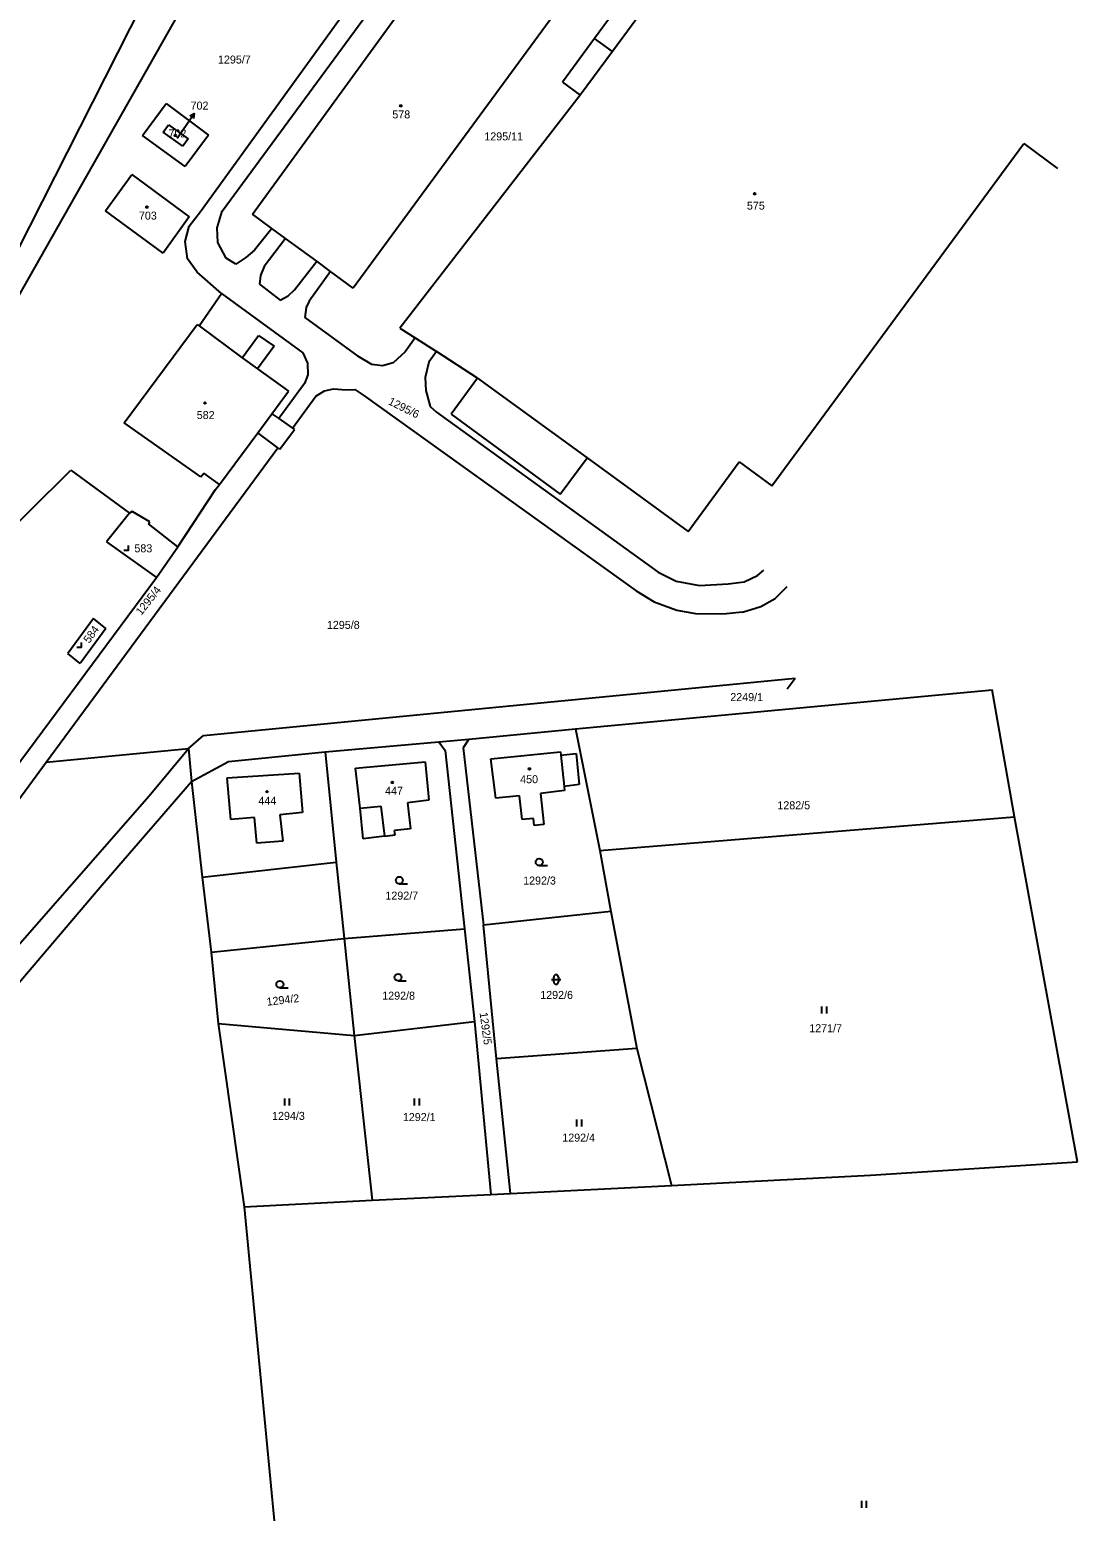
# Model space of a CAD drawing. Extents: x -717507 to -715515, y -957700 to -954941.
# Drawn here: x -716724.1 to -716501.6, y -957047 to -956732.3 of the extents above; entities that cross this region are included whole.
import ezdxf

# ---------------------------------------------------------------- set-up
doc = ezdxf.new("R2010")
doc.units = 0
for name, color, linetype in [('Hranice parcel', 7, 'Continuous'), ('Parcelní čísla', 7, 'Continuous'), ('Pop  PČ popisy', 7, 'Continuous'), ('Vnitřní kresba', 7, 'Continuous'), ('Značky budov', 7, 'Continuous'), ('Značky kultur', 7, 'Continuous')]:
    doc.layers.add(name, color=color, linetype=linetype)

msp = doc.modelspace()

# ---------------------------------------------------------------- linework, layer by layer
at = {"layer": 'Hranice parcel'}
for points in [[(-716687.81, -956770.92), (-716623.91, -956682.42)], [(-716676.78, -956771.51), (-716629.89, -956706.87)], [(-716774.89, -956874.26), (-716692.04, -956710.7)], [(-716774.89, -956874.26), (-716682.29, -956710.93)], [(-716597.24, -956724.68), (-716604.17, -956734.14)], [(-716612.06, -956728.11), (-716655.41, -956787.18)], [(-716604.17, -956734.14), (-716611, -956743.46)], [(-716611, -956743.46), (-716607.19, -956746.24)], [(-716607.19, -956746.24), (-716645.55, -956795.69)], [(-716700.15, -956754.8), (-716695.15, -956748)], [(-716695.15, -956748), (-716686.17, -956754.68)], [(-716691.1, -956761.38), (-716700.15, -956754.8)], [(-716686.17, -956754.68), (-716691.1, -956761.38)], [(-716708.01, -956770.8), (-716702.42, -956763.08)], [(-716702.42, -956763.08), (-716690.22, -956772.04)], [(-716695.78, -956779.76), (-716708.01, -956770.8)], [(-716690.22, -956772.04), (-716695.78, -956779.76)], [(-716690.22, -956774.01), (-716687.81, -956770.92)], [(-716672.7, -956774.5), (-716676.78, -956771.51)], [(-716691.08, -956777.29), (-716690.22, -956774.01)], [(-716669.79, -956776.63), (-716672.7, -956774.5)], [(-716690.64, -956780.99), (-716691.08, -956777.29)], [(-716663.15, -956781.5), (-716669.79, -956776.63)], [(-716688.57, -956783.83), (-716690.64, -956780.99)], [(-716660.21, -956783.66), (-716663.15, -956781.5)], [(-716683.37, -956788.32), (-716688.57, -956783.83)], [(-716660.21, -956783.66), (-716664.8, -956789.96)], [(-716655.41, -956787.18), (-716660.21, -956783.66)], [(-716688.15, -956795.23), (-716683.37, -956788.32)], [(-716683.37, -956788.32), (-716666.14, -956800.91)], [(-716664.8, -956789.96), (-716665.41, -956791.32)], [(-716665.41, -956791.32), (-716665.68, -956793.43)], [(-716665.68, -956793.43), (-716654.44, -956801.66)], [(-716704.06, -956815.79), (-716688.54, -956794.95)], [(-716688.54, -956794.95), (-716688.15, -956795.23)], [(-716645.55, -956795.69), (-716642.28, -956797.78)], [(-716642.28, -956797.78), (-716644.41, -956800.74)], [(-716642.28, -956797.78), (-716637.75, -956800.68)], [(-716637.75, -956800.68), (-716639.33, -956802.9)], [(-716666.14, -956800.91), (-716665.13, -956803.15)], [(-716665.13, -956803.15), (-716665.05, -956805.6)], [(-716651.44, -956803.41), (-716654.44, -956801.66)], [(-716649.22, -956803.73), (-716651.44, -956803.41)], [(-716646.96, -956803.08), (-716649.22, -956803.73)], [(-716644.41, -956800.74), (-716646.96, -956803.08)], [(-716639.33, -956802.9), (-716640.12, -956806.15)], [(-716665.05, -956805.6), (-716665.76, -956807.45)], [(-716640.12, -956806.15), (-716639.96, -956808.92)], [(-716665.76, -956807.45), (-716671.2, -956814.91)], [(-716668.28, -956816.93), (-716663.38, -956810.15)], [(-716663.38, -956810.15), (-716661.53, -956809.03)], [(-716661.53, -956809.03), (-716659.57, -956808.59)], [(-716659.57, -956808.59), (-716656.92, -956808.82)], [(-716656.92, -956808.82), (-716655.08, -956808.7)], [(-716655.08, -956808.7), (-716653.14, -956810.01)], [(-716653.14, -956810.01), (-716595.32, -956851.51)], [(-716639.96, -956808.92), (-716639.05, -956812.33)], [(-716639.05, -956812.33), (-716637.71, -956813.53)], [(-716687.74, -956827.3), (-716704.06, -956815.79)], [(-716671.2, -956814.91), (-716668.28, -956816.93)], [(-716637.71, -956813.53), (-716590.68, -956847.53)], [(-716683.8, -956828.88), (-716675.69, -956817.92)], [(-716671.41, -956821.12), (-716675.69, -956817.92)], [(-716671.03, -956821.39), (-716667.91, -956817.19)], [(-716668.28, -956816.93), (-716667.91, -956817.19)], [(-716720.61, -956887.89), (-716671.41, -956821.12)], [(-716671.03, -956821.39), (-716671.41, -956821.12)], [(-716742.01, -956852.17), (-716715.4, -956825.86)], [(-716715.4, -956825.86), (-716702.92, -956834.98)], [(-716687.74, -956827.3), (-716687.16, -956826.51)], [(-716683.8, -956828.88), (-716687.16, -956826.51)], [(-716684.69, -956829.98), (-716683.8, -956828.88)], [(-716692.66, -956842.15), (-716684.69, -956829.98)], [(-716702.92, -956834.98), (-716707.79, -956841.09)], [(-716702.36, -956834.64), (-716702.92, -956834.98)], [(-716698.57, -956836.87), (-716702.36, -956834.64)], [(-716698.87, -956837.26), (-716698.57, -956836.87)], [(-716692.66, -956842.15), (-716698.87, -956837.26)], [(-716707.79, -956841.09), (-716697.16, -956848.67)], [(-716697.16, -956848.67), (-716692.66, -956842.15)], [(-716590.68, -956847.53), (-716586.86, -956849.41)], [(-716569.58, -956848.22), (-716568.23, -956847.12)], [(-716733.6, -956897.64), (-716697.16, -956848.67)], [(-716586.86, -956849.41), (-716581.87, -956850.39)], [(-716581.87, -956850.39), (-716575.78, -956849.98)], [(-716575.78, -956849.98), (-716572.39, -956849.57)], [(-716572.39, -956849.57), (-716569.58, -956848.22)], [(-716565.83, -956853.11), (-716563.26, -956850.6)], [(-716595.32, -956851.51), (-716591.53, -956853.83)], [(-716591.53, -956853.83), (-716586.69, -956855.58)], [(-716568.86, -956854.83), (-716565.83, -956853.11)], [(-716586.69, -956855.58), (-716582.73, -956856.28)], [(-716582.73, -956856.28), (-716576.24, -956856.38)], [(-716572.74, -956856.03), (-716576.24, -956856.38)], [(-716572.74, -956856.03), (-716568.86, -956854.83)], [(-716710.59, -956857.4), (-716716.01, -956864.82)], [(-716707.97, -956859.52), (-716713.39, -956866.94)], [(-716707.97, -956859.52), (-716710.59, -956857.4)], [(-716713.39, -956866.94), (-716716.01, -956864.82)], [(-716687.19, -956882.25), (-716561.58, -956870.06)], [(-716608.23, -956880.78), (-716519.75, -956872.5)], [(-716563.26, -956872.32), (-716561.58, -956870.06)], [(-716515.02, -956899.53), (-716519.75, -956872.5)], [(-716690.36, -956885), (-716687.19, -956882.25)], [(-716630.83, -956882.99), (-716608.23, -956880.78)], [(-716608.23, -956880.78), (-716603.05, -956906.66)], [(-716720.61, -956887.89), (-716690.36, -956885)], [(-716698.73, -956895.06), (-716690.36, -956885)], [(-716690.36, -956885), (-716689.75, -956892.02)], [(-716681.88, -956887.75), (-716661.39, -956885.66)], [(-716661.39, -956885.66), (-716637.26, -956883.57)], [(-716661.39, -956885.66), (-716659.04, -956909.14)], [(-716637.26, -956883.57), (-716630.83, -956882.99)], [(-716637.26, -956883.57), (-716635.9, -956885.44)], [(-716635.9, -956885.44), (-716631.8, -956923.29)], [(-716630.83, -956882.99), (-716632.07, -956884.86)], [(-716632.07, -956884.86), (-716627.73, -956922.5)], [(-716732.5, -956904.02), (-716720.61, -956887.89)], [(-716689.75, -956892.02), (-716681.88, -956887.75)], [(-716654.92, -956889.18), (-716640.17, -956887.79)], [(-716640.17, -956887.79), (-716639.37, -956895.98)], [(-716626.2, -956887.15), (-716611.42, -956885.72)], [(-716625.14, -956895.52), (-716626.2, -956887.15)], [(-716611.42, -956885.72), (-716611.34, -956886.41)], [(-716611.34, -956886.41), (-716608.1, -956886.05)], [(-716608.1, -956886.05), (-716607.41, -956892.62)], [(-716653.96, -956897.69), (-716654.92, -956889.18)], [(-716731.68, -956932.56), (-716698.73, -956895.06)], [(-716708.83, -956914), (-716689.75, -956892.02)], [(-716689.75, -956892.02), (-716687.47, -956912.3)], [(-716620.11, -956895.07), (-716625.14, -956895.52)], [(-716619.52, -956900.07), (-716620.11, -956895.07)], [(-716610.56, -956893.87), (-716615.65, -956894.55)], [(-716615.65, -956894.55), (-716614.95, -956901.13)], [(-716607.41, -956892.62), (-716610.65, -956893.02)], [(-716610.65, -956893.02), (-716610.56, -956893.87)], [(-716653.29, -956904.16), (-716653.96, -956897.69)], [(-716639.37, -956895.98), (-716643.89, -956896.53)], [(-716643.89, -956896.53), (-716643.28, -956902.02)], [(-716617.14, -956899.85), (-716619.52, -956900.07)], [(-716616.99, -956901.31), (-716617.14, -956899.85)], [(-716614.95, -956901.13), (-716616.99, -956901.31)], [(-716603.05, -956906.66), (-716515.02, -956899.53)], [(-716501.64, -956972.78), (-716515.02, -956899.53)], [(-716648.79, -956903.62), (-716653.29, -956904.16)], [(-716648.79, -956903.62), (-716646.53, -956903.35)], [(-716643.28, -956902.02), (-716646.62, -956902.43)], [(-716646.53, -956903.35), (-716646.62, -956902.43)], [(-716603.05, -956906.66), (-716600.73, -956919.64)], [(-716687.47, -956912.3), (-716659.04, -956909.14)], [(-716659.04, -956909.14), (-716657.36, -956925.37)], [(-716729.15, -956938.03), (-716708.83, -956914)], [(-716687.47, -956912.3), (-716685.58, -956928.22)], [(-716600.73, -956919.64), (-716627.73, -956922.5)], [(-716600.73, -956919.64), (-716595.16, -956948.69)], [(-716657.36, -956925.37), (-716631.8, -956923.29)], [(-716631.8, -956923.29), (-716629.67, -956942.99)], [(-716625.01, -956950.87), (-716627.73, -956922.5)], [(-716657.36, -956925.37), (-716655.18, -956945.98)], [(-716685.58, -956928.22), (-716684.08, -956943.4)], [(-716684.08, -956943.4), (-716655.18, -956945.98)], [(-716684.08, -956943.4), (-716678.56, -956982.31)], [(-716655.18, -956945.98), (-716629.67, -956942.99)], [(-716629.67, -956942.99), (-716626.19, -956979.69)], [(-716655.18, -956945.98), (-716651.41, -956980.95)], [(-716595.16, -956948.69), (-716625.01, -956950.87)], [(-716622.01, -956979.48), (-716625.01, -956950.87)], [(-716595.16, -956948.69), (-716587.86, -956977.78)], [(-716545.54, -956975.62), (-716501.64, -956972.78)], [(-716587.86, -956977.78), (-716545.54, -956975.62)], [(-716651.41, -956980.95), (-716626.19, -956979.69)], [(-716626.19, -956979.69), (-716622.01, -956979.48)], [(-716622.01, -956979.48), (-716587.86, -956977.78)], [(-716678.56, -956982.31), (-716651.41, -956980.95)], [(-716678.56, -956982.31), (-716668.42, -957088.24)]]:
    msp.add_lwpolyline(points, dxfattribs=at)
at = {"layer": 'Pop  PČ popisy'}
for points in [[(-716690.87, -956752.55), (-716689.16, -956750.09)], [(-716690.14, -956750.62), (-716689.16, -956750.09), (-716689.32, -956751.19)], [(-716692.83, -956755.37), (-716690.87, -956752.55)]]:
    msp.add_lwpolyline(points, dxfattribs=at)
at = {"layer": 'Vnitřní kresba'}
for points in [[(-716683.26, -956770.85), (-716617.42, -956681.21)], [(-716579.04, -956707.96), (-716600.35, -956736.94)], [(-716600.35, -956736.94), (-716604.17, -956734.14)], [(-716600.35, -956736.94), (-716607.19, -956746.24)], [(-716695.78, -956754.07), (-716694.64, -956752.48)], [(-716694.64, -956752.48), (-716690.46, -956755.47)], [(-716691.61, -956757.07), (-716695.78, -956754.07)], [(-716690.46, -956755.47), (-716691.61, -956757.07)], [(-716566.5, -956829.17), (-716513.03, -956756.44)], [(-716513.03, -956756.44), (-716505.85, -956761.75)], [(-716684.31, -956774.39), (-716683.26, -956770.85)], [(-716684.15, -956777.5), (-716684.31, -956774.39)], [(-716672.7, -956774.5), (-716676.39, -956779.12)], [(-716682.38, -956780.86), (-716684.15, -956777.5)], [(-716669.79, -956776.63), (-716674.35, -956782.59)], [(-716680.34, -956782.13), (-716682.38, -956780.86)], [(-716678.22, -956780.7), (-716680.34, -956782.13)], [(-716676.39, -956779.12), (-716678.22, -956780.7)], [(-716667.88, -956787.57), (-716663.15, -956781.5)], [(-716675.13, -956784.54), (-716675.32, -956786.33)], [(-716674.35, -956782.59), (-716675.13, -956784.54)], [(-716675.32, -956786.33), (-716670.94, -956789.72)], [(-716669.26, -956788.84), (-716667.88, -956787.57)], [(-716670.94, -956789.72), (-716669.26, -956788.84)], [(-716688.15, -956795.23), (-716679.02, -956801.97)], [(-716679.02, -956801.97), (-716675.5, -956797.28)], [(-716675.5, -956797.28), (-716672.21, -956799.53)], [(-716672.21, -956799.53), (-716675.76, -956804.32)], [(-716629, -956806.29), (-716637.75, -956800.68)], [(-716679.02, -956801.97), (-716675.76, -956804.32)], [(-716675.76, -956804.32), (-716669.14, -956809.08)], [(-716629, -956806.29), (-716634.59, -956814)], [(-716629, -956806.29), (-716605.76, -956823.22)], [(-716672.69, -956813.88), (-716669.14, -956809.08)], [(-716675.69, -956817.92), (-716672.69, -956813.88)], [(-716672.69, -956813.88), (-716671.2, -956814.91)], [(-716634.59, -956814), (-716611.49, -956830.97)], [(-716611.49, -956830.97), (-716605.76, -956823.22)], [(-716605.76, -956823.22), (-716584.27, -956838.87)], [(-716584.27, -956838.87), (-716573.47, -956824.09)], [(-716573.47, -956824.09), (-716566.5, -956829.17)], [(-716611.34, -956886.41), (-716610.65, -956893.02)], [(-716682.16, -956891.24), (-716666.92, -956890.22)], [(-716681.37, -956900.06), (-716682.16, -956891.24)], [(-716666.92, -956890.22), (-716666.21, -956898.6)], [(-716653.96, -956897.69), (-716649.56, -956897.26)], [(-716649.56, -956897.26), (-716648.79, -956903.62)], [(-716676.39, -956899.66), (-716681.37, -956900.06)], [(-716675.87, -956905.09), (-716676.39, -956899.66)], [(-716666.21, -956898.6), (-716670.98, -956899.06)], [(-716670.98, -956899.06), (-716670.37, -956904.69)], [(-716670.37, -956904.69), (-716675.87, -956905.09)], [(-716685.58, -956928.22), (-716657.36, -956925.37)]]:
    msp.add_lwpolyline(points, dxfattribs=at)
at = {"layer": 'Značky budov'}
for centre in [(-716645.31, -956748.47), (-716693.19, -956754.76), (-716570.18, -956767.16), (-716699.23, -956769.99), (-716686.9, -956811.59), (-716617.99, -956889.31), (-716673.72, -956894.15), (-716647.12, -956892.19)]:
    msp.add_circle(centre, 0.175, dxfattribs=at)
at = {"layer": 'Značky kultur'}
for points in [[(-716704.12, -956842.87), (-716703.12, -956842.87), (-716703.12, -956841.87)], [(-716714.1, -956863.46), (-716713.1, -956863.46), (-716713.1, -956862.46)], [(-716615.91, -956909.87), (-716614.16, -956909.87)], [(-716645.63, -956913.71), (-716643.88, -956913.71)], [(-716670.99, -956935.83), (-716669.24, -956935.83)], [(-716645.89, -956934.33), (-716644.14, -956934.33)], [(-716613.32, -956934.05), (-716611.32, -956934.05)], [(-716612.82, -956934.55), (-716612.82, -956933.55)], [(-716611.82, -956933.55), (-716611.82, -956934.55)], [(-716555.9, -956941.29), (-716555.9, -956939.79)], [(-716554.86, -956941.29), (-716554.86, -956939.79)], [(-716669.97, -956960.84), (-716669.97, -956959.34)], [(-716668.93, -956960.84), (-716668.93, -956959.34)], [(-716642.39, -956960.8), (-716642.39, -956959.3)], [(-716641.35, -956960.8), (-716641.35, -956959.3)], [(-716607.92, -956965.27), (-716607.92, -956963.77)], [(-716606.88, -956965.27), (-716606.88, -956963.77)], [(-716547.43, -957046.29), (-716547.43, -957044.79)], [(-716546.39, -957046.29), (-716546.39, -957044.79)]]:
    msp.add_lwpolyline(points, dxfattribs=at)
for centre in [(-716615.91, -956909.12), (-716645.63, -956912.96), (-716645.89, -956933.58), (-716670.99, -956935.08)]:
    msp.add_circle(centre, 0.75, dxfattribs=at)
for centre, start, end in [((-716612.32, -956933.55), 0.101, 180.0014), ((-716612.32, -956934.55), 180.1024, 0.0029)]:
    msp.add_arc(centre, 0.5, start, end, dxfattribs=at)

# ---------------------------------------------------------------- texts
at = {"layer": 'Parcelní čísla'}
for s, p in [('1295/7', (-716684.13, -956739.49)), ('702', (-716689.95, -956749.27)), ('578', (-716647.11, -956751.14)), ('702', (-716694.64, -956755.17)), ('1295/11', (-716627.57, -956755.81)), ('575', (-716571.81, -956770.52)), ('703', (-716700.92, -956772.64)), ('582', (-716688.64, -956815)), ('583', (-716701.88, -956843.31)), ('1295/8', (-716661, -956859.58)), ('2249/1', (-716575.34, -956874.91)), ('450', (-716619.96, -956892.36)), ('447', (-716648.65, -956894.81)), ('444', (-716675.54, -956896.91)), ('1282/5', (-716565.34, -956897.89)), ('1292/3', (-716619.33, -956913.88)), ('1292/7', (-716648.58, -956917.08)), ('1292/8', (-716649.25, -956938.34)), ('1292/6', (-716615.7, -956938.18)), ('1271/7', (-716558.57, -956945.25)), ('1294/3', (-716672.65, -956963.87)), ('1292/1', (-716644.87, -956964.12)), ('1292/4', (-716611.02, -956968.49))]:
    msp.add_text(s, height=1.7, dxfattribs=at).set_placement(p)
for s, rotation, p in [('1295/6', 333.4027, (-716648.13, -956811.8)), ('1295/4', 51.7004, (-716700.42, -956856.82)), ('584', 54.5004, (-716711.47, -956862.77)), ('1294/2', 6.7001, (-716673.7, -956939.64)), ('1292/5', 277.9022, (-716628.59, -956941.13))]:
    msp.add_text(s, height=1.7, rotation=rotation, dxfattribs=at).set_placement(p)

doc.saveas('drawing.dxf')
